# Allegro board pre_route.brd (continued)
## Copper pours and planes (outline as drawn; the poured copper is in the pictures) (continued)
XCVR_RX_N3C on TOP (solid shape): 263.03,247.12 263.04,247.12 263.19,246.89 263.25,246.61 263.25,244.26 263.72,242.76 263.73,242.67 263.74,242.63 263.74,242.56 263.24,242.56 263.24,242.27 262.52,242.27 262.52,242.57 262.04,242.57 262.04,242.67 262.06,242.77 262.16,243.14 262.29,243.5 262.53,244.25 262.53,246.62 262.38,247.76 262.39,247.76
XCVR_RX_N<1> on TOP (solid shape): 322.61,98.01 322.61,97.63 322.45,97.47 321.92,97.47 321.91,97.47 321.76,97.47 321.15,97.65 321.15,98 321.75,98.18 321.76,98.18 322.44,98.18
XCVR_RX_N<16> on TOP (solid shape): 312.34,249.81 312.34,249.3 312.17,249.2 311.44,249.2 310.77,249.19 310.6,249.26 310.53,249.43 310.57,249.57 310.69,249.66 311.43,249.91 312.17,249.91
XCVR_RX_N<17> on TOP (solid shape): 312.34,232.66 312.34,232.16 312.17,232.05 311.44,232.05 310.77,232.04 310.6,232.11 310.53,232.28 310.57,232.42 310.69,232.51 311.43,232.77 312.17,232.77
XCVR_RX_N<18> on TOP (solid shape): 312.34,266.95 312.34,266.45 312.17,266.34 311.44,266.34 310.77,266.33 310.6,266.4 310.53,266.57 310.57,266.71 310.69,266.8 311.43,267.06 312.17,267.06
XCVR_RX_N<19> on TOP (solid shape): 312.34,284.1 312.34,283.59 312.17,283.49 311.44,283.49 310.77,283.48 310.6,283.55 310.53,283.72 310.57,283.86 310.69,283.95 311.43,284.2 312.17,284.2
XCVR_RX_P0C on TOP (solid shape): 330.28,67 328.5,67 326.73,67.15 326.73,67.5 328.5,67.64 330.28,67.64
XCVR_RX_P0C on TOP (solid shape): 324.94,67.5 324.94,67.15 324.07,66.96 323.43,66.96 323.22,67.18 323.22,67.46 323.43,67.68 324.07,67.68
XCVR_RX_P1C on TOP (solid shape): 330.28,82.27 328.5,82.27 326.73,82.41 326.73,82.76 328.5,82.91 330.28,82.91
XCVR_RX_P1C on TOP (solid shape): 324.8,82.77 324.8,82.41 323.93,82.23 323.28,82.23 323.09,82.42 323.09,82.75 323.28,82.94 323.93,82.94
XCVR_RX_P2C on TOP (solid shape): 275.96,255.27 276.44,255.27 276.44,255.17 276.42,255.07 276.32,254.7 276.19,254.34 275.95,253.58 275.95,253.58 275.95,251.52 275.89,251.26 275.74,251.03 274.96,250.25 274.96,250.25 274.49,250.72 274.49,250.78 275.23,251.53 275.23,253.58 274.76,255.08 274.75,255.16 274.74,255.21 274.74,255.28 275.24,255.28 275.24,255.56 275.96,255.56
XCVR_RX_P3C on TOP (solid shape): 263.26,255.27 263.74,255.27 263.74,255.17 263.72,255.07 263.62,254.7 263.49,254.34 263.25,253.58 263.25,251.47 263.19,251.21 263.04,250.98 262.26,250.2 261.76,250.7 262.53,251.48 262.53,253.58 262.06,255.08 262.05,255.16 262.04,255.21 262.04,255.28 262.54,255.28 262.54,255.56 263.26,255.56
XCVR_RX_P<0> on TOP (solid shape): 322.71,67.44 322.71,67.18 322.49,66.96 322.01,66.96 321.85,66.96 321.24,67.14 321.24,67.5 321.85,67.67 321.85,67.68 322.47,67.68
XCVR_RX_P<1> on TOP (solid shape): 322.58,82.8 322.58,82.42 322.39,82.23 321.87,82.23 321.87,82.23 321.71,82.23 321.1,82.41 321.1,82.76 321.7,82.94 321.71,82.94 322.44,82.94
XCVR_RX_P<2> on TOP (solid shape): 274.45,250.19 274.45,249.94 274.41,249.9 274.51,249.8 274.08,249.37 274.08,249.36 273.97,249.29 273.84,249.26 273.07,249.27 272.9,249.33 272.83,249.5 272.83,249.52 272.88,249.66 273.01,249.74 273.57,249.86 273.94,250.24 273.94,250.24 274.01,250.31 274.1,250.22 274.32,250.32
XCVR_RX_P<3> on TOP (solid shape): 261.99,249.93 261.35,249.29 261.35,249.28 261.24,249.21 261.11,249.18 260.34,249.19 260.18,249.26 260.11,249.42 260.11,249.44 260.15,249.58 260.28,249.66 260.84,249.79 261.21,250.16 261.21,250.16 261.49,250.43
XCVR_RX_P<16> on TOP (solid shape): 310.8,248.78 311.44,248.64 312.17,248.64 312.34,248.54 312.34,248.03 312.17,247.93 311.44,247.93 310.65,248.33 310.59,248.37 310.54,248.45 310.53,248.54 310.6,248.71 310.77,248.78
XCVR_RX_P<17> on TOP (solid shape): 310.8,231.63 311.44,231.5 312.17,231.5 312.34,231.39 312.34,230.89 312.17,230.78 311.44,230.78 310.65,231.19 310.59,231.23 310.54,231.31 310.53,231.39 310.6,231.56 310.77,231.64
XCVR_RX_P<18> on TOP (solid shape): 310.8,265.92 311.44,265.79 312.17,265.79 312.34,265.68 312.34,265.18 312.17,265.07 311.44,265.07 310.65,265.48 310.59,265.52 310.54,265.6 310.53,265.68 310.6,265.85 310.77,265.93
XCVR_RX_P<19> on TOP (solid shape): 310.8,283.07 311.44,282.93 312.17,282.93 312.34,282.83 312.34,282.32 312.17,282.22 311.44,282.22 310.65,282.62 310.59,282.66 310.54,282.74 310.53,282.83 310.6,283 310.77,283.07
XCVR_TX_N<0> on TOP (solid shape): 330.28,112.75 328.5,112.75 326.73,112.89 326.73,113.24 328.5,113.39 330.28,113.39
XCVR_TX_N<1> on TOP (solid shape): 330.28,21.17 328.51,21.17 326.74,21.32 326.74,21.67 328.51,21.81 330.28,21.81
XCVR_TX_N<2> on TOP (solid shape): 289.12,242.76 289.13,242.67 289.14,242.63 289.14,242.56 288.64,242.56 288.64,242.27 287.92,242.27 287.92,242.57 287.44,242.57 287.44,242.67 287.46,242.77 287.56,243.14 287.69,243.5 287.93,244.25 287.93,244.26 288.65,244.26
XCVR_TX_N<3> on TOP (solid shape): 251.02,242.76 251.03,242.67 251.04,242.63 251.04,242.56 250.54,242.56 250.54,242.27 249.82,242.27 249.82,242.57 249.34,242.57 249.34,242.67 249.36,242.77 249.46,243.14 249.59,243.5 249.83,244.25 249.83,244.26 250.55,244.26
XCVR_TX_P<0> on TOP (solid shape): 330.28,127.99 328.5,127.99 326.73,128.13 326.73,128.48 328.5,128.63 330.28,128.63
XCVR_TX_P<1> on TOP (solid shape): 330.28,36.42 328.5,36.42 326.73,36.56 326.73,36.91 328.5,37.06 330.28,37.06
XCVR_TX_P<2> on TOP (solid shape): 288.66,255.27 289.14,255.27 289.14,255.17 289.12,255.07 289.02,254.7 288.89,254.34 288.65,253.58 288.65,253.58 287.93,253.58 287.46,255.08 287.45,255.16 287.44,255.21 287.44,255.28 287.94,255.28 287.94,255.56 288.66,255.56
XCVR_TX_P<3> on TOP (solid shape): 250.56,255.27 251.04,255.27 251.04,255.17 251.02,255.07 250.92,254.7 250.79,254.34 250.55,253.58 250.55,253.58 249.83,253.58 249.36,255.08 249.35,255.16 249.34,255.21 249.34,255.28 249.84,255.28 249.84,255.56 250.56,255.56
N24962500 on TOP (solid shape): 50.29,259.46 50.29,256.54 50.1,256.35 45.4,256.35 45.21,256.54 45.21,259.33 45.4,259.52 50.23,259.52

Small or netless copper shapes (teardrops, artwork), in the pictures only: 23 on TOP

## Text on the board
BOTTOM: COPYRIGHT   2003 | 100-0365000-01 REV.C | 18
Ref Des/Silkscreen Bottom: 9 | 6 | 5 | 1 | 3.3V PMC INTERFACE
User.Comments: REV. | FIGURE | 86.0 | 90.0 | 94.0 | SIZE | 62.0 | 67.0 | 55.0 | 118.0 | 126.0 | 138.0 | 47.0 | 36.0 | 42.0 | 49.0 | 52.0 | 170.0 | 32.0 | 10.0 | 56.0 | 120.0 | 125.0 | 128.0 | 24.0 | 28.0 | 85.0 | 21.0 | 2.0 | TOLERANCE | 3.0 | DRILL CHART (ALL UNITS ARE IN INCHES) | NON-PLATED | PLATED | 8 | 2 | 5 | QTY | 10 | 4 | 54 | 339 | 18 | 19 | 6112 | 212 | 28 | 249 | 11 | 6 | 362 | 256 | C
TOP: 1
Ref Des/Assembly Top: U53 | PRIMARY SIDE | SECONDARY SIDE
L2_GND1: 2
L3_IS1: 3
L4_IS2: 4
L5_PWR1: 5
L6_IS3: 6
L7_IS4: 7
L8_GND2: 8
L9_IS5: 9
L10_IS6: 10
L11_PWR2: 11
L12_IS7: 12
L13_IS8: 13
L14_GND3: 14
L15_IS9: 15
L16_IS10: 16
L17_PWR3: 17
DIMENSION: (2pl) | .250
User.11: 28. DELIVERY, PROVIDE 6 BOARDS TO ALTERA AND 2 BOARDS TO FLEXTRONICS FOR SMT AND | OF 100 MILS FROM ANY OTHER COPPER FEATURE ON THE BOARD. | THERMAL TESTING. | 26. COPPER THIEVING SHALL BE APPLIED WHEREVER REQUIRED BUT MUST HAVE A SPACING | 27. REMOVE ALL UNCONNECTED VIA PADS IN INNER LAYERS. | 22. VENDOR TO PROVIDE 2 SOLDER SAMPLES WITH FIRST SHIPMENT. | 23. DETAILS NOT SPECIFIED ARE AT MANUFACTURER'S OPTION, HOWEVER | FINAL APPROVAL MUST BE OBTAINED. | 24  THESE HOLES MAY BE PLATED SHUT OR SOLDER FILLED. | 25. PLUG VIA HOLES FROM         SIDE WITH SR-1000 OR EQUIVALENT MATERIAL, CLEAR | UV MASK IS ACCEPTABLE. PLUG HEIGHT NOT TO EXCEED 0.003 OVER FINISHED PLATING HEIGHT. | 21. VENDOR TO PROVIDE                     ONE CROSS SECTION PER LOT WITH SHIPMENT. | INCHES MINIMUM ELECTROLESS NICKEL (Ni) FOLLOWED BY 3-8 MICRO INCHES | IMMERSION GOLD (Au). | 17  FINISH IS SOLDER MASK OVER BARE COPPER (SMOBC) BOTH SIDES WITH 150 MICRO | 18  SILKSCREEN USING WHITE NONCONDUCTIVE INK. NO INK TO APPEAR ON EXPOSED | COPPER SUCH AS PLATED THROUGH HOLE PADS AND SURFACE MOUNT LANDS. INK | ON SOLDER MASK COVERED PADS IS PERMISSIBLE. CLIPPING OF SILKSCREEN | 0.008 MAX. FROM PADS IS PERMITTED IF REQUIRED. | 19. 100% CONTINUITY AND ISOLATION ELECTRICAL TESTING PER CURRENT IPC TEST METHODS | REQUIRED FOR EVERY PCB. FINAL PCB TEST DATA MUST BE CROSS-REFERENCED TO | IPC-D-356 FILE, NEUTRAL FILE OR NETLIST PROVIDED. | 20  CONTROLLED IMPEDANCE LINES ARE AS FOLLOWS: | NOTES UNLESS OTHERWISE SPECIFIED: | 1. ALTERA PCB PART NUMBER: P/N 100-0365000-01 REV.C | 2. THIS DRAWING IS VIEWED FROM THE PRIMARY OR TOP SIDE OF PCB. | 3  FABRICATION OF THIS PCB SHALL BE IN CONFORMANCE WITH THE FOLLOWING SPECIFICATIONS: | 4. FABRICATION OF THIS PCB TO BE ACCEPTABLE TO IPC-A-600 CLASS 2(LATEST REVISION). | 5. ALL DIMENSIONAL LIMITS APPLY AFTER PLATING OR PROCESSING. | 6. TOLERANCES OF DATUM HOLE TO:  BOARD EDGE LOCATIONS +/- 0.010. | DRILLED HOLE LOCATIONS +/- 0.003. | V-SCORE LOCATIONS +/- 0.010 (IF APPLICABLE). | 7  BASE MATERIAL:                , MIN. Tg OF     DEGREES C. | 8. FLAME CLASS: UL 94V-0 & MUST MEET REQUIREMENTS OF UL796. | 9. MANUFACTURER MUST BE UL RECOGNIZED TO PRODUCE THIS PRODUCT SUCH THAT | IT MEETS 170 DEGREES CELSIUS MAXIMUM OPERATING TEMPERATURE (MOT). | 10  THE FOLLOWING MUST BE MARKED OR ETCHED ON SECONDARY SIDE OF PCB IN AREA SHOWN: | DATE CODE. | UL RECOGNIZED VENDOR ID, UL TYPE DESIGNATION AND/OR MARKINGS WHICH REFLECT | THE SPECIFIED FLAME CLASS AND MAXIMUM OPERATING TEMPERATURE RATINGS. | 11. BOW & TWIST SHALL BE DETERMINED BY PHYSICAL MEASUREMENT AND PERCENTAGE CALCULATION | IN ACCORDANCE WITH IPC-TM-650, METHOD 2.4.22. BOW AND TWIST MAY NOT EXCEED 0.7%. | 12. HOLE/SLOT PLATING = 0.001 MIN. AVERAGE / 0.0008 ABSOLUTE MIN. PLATING. | HOLE/SLOT DIAMETERS ARE SPECIFIED AFTER PLATING (SEE HOLE SCHEDULE). | 13. SMEAR REMOVAL SHALL NOT ETCHBACK GREATER THAN 0.001. | 14. INTERNAL ANNULAR RING 0.001 MINIMUM. EXTERNAL ANNULAR RING 0.002 MINIMUM. BOTH | ARE MEASURED AT LINE TO PAD ENTRY. NON-FUNCTIONAL INNER LAYER PADS MAY BE REMOVED. | SNOWMAN/TEAR DROPPING OF TRACE TO PAD JUNCTION IS PERMITTED PROVIDED MINIMUM | METAL-TO-METAL ARTWORK SPACINGS ARE NOT COMPROMISED. | 15. FINISHED CONDUCTOR WIDTH NOT TO BE REDUCED MORE THAN 20% OF MINIMUM WIDTH FROM | ARTWORK SUPPLIED. FINISHED CONDUCTOR SPACING NOT TO BE REDUCED MORE THAN 20% OF | MINIMUM SPACING FROM ARTWORK SUPPLIED. | 16  SOLDER MASK IS LIQUID PHOTO IMAGEABLE WITH GLOSSY FINISH AND COLORED GREEN | ACCORDANCE WITH IPC-SM-840C CLASS T. REGISTRATION TO BE WITHIN +/-0.003 OF ITS | RESPECTIVE OUTER CIRCUIT LAYERS. VENDOR MAY ADJUST SOLDERMASK WHEREVER SOLDERMASK | PAD ARE THE SAME SIZE (1:1) TO PROVIDE UP TO .003" MAXIMUM CLEARANCE FROM MASK TO | PAD PROVIDED NO ADJACENT COPPER IS EXPOSED AND NO CONFLICT IS PRODUCED WITH ANY | STATED "VIA TENTING/PLUGGING" REQUIREMENTS (IF APPLICABLE). | NOTE THAT THERE ARE AREAS ON PRIMARY SIDE THAT ARE CLEAR OF SOLDERMASK. | SECONDARY SIDE WILL REQUIRED VIAS TO BE EXPOSED. | IN | 10 | 20 | 24 | 16 | 7 | 3 | 18 | 17 | DETAIL | SCALE: NONE | (CROSS SECTION) | A
User.41: J. MANNING
User.43: 9330 Scranton Road | Suite 400 | San Diego, CA | 92121 | NOTES: UNLESS OTHERWISE SPECIFIED | 1. | 2. | 3. | 4. | ASSEMBLE BOARD PER IPC-A-610(LATEST REVISION) STANDARD | HANDLE MOISTURE SENSITIVE DEVICES(MSD) PER MANUFACTURE'S | CALL OUT ON MSD LABEL. IF MSD LABEL IS MISSING OR NOT LEGIBLE | THEN ALL PLASTIC PACKAGED COMPONENTS ARE TO BE CONSIDERED MSD | LEVEL 6 AND USE EIA/JEP 113-A FOR HANDLING. | REWORK MUST BE APPROVED BY CUSTOMER BEFORE BEING ACCEPTIBLE. | USE IPC-R-700(LATEST REVISION) FOR ALL PCBA REWORK APPROVED. | SQUARE PIN PADS DENOTE PIN 1 OF ICs/CONNECTORS, POSITIVE END | FOR CAPACITORS OR CATHODE END FOR DIODES. | 130-0365000-01 | Altera Corporation
User.45: ETHERNET | 10/100 | GND | POWER | ATX | TEL_ON | GND_PLL | ATX_ON | STRATIX_PB_[0:3] | 3.3V_LIN_EN | GX_CLR | STRATIX_GX_PB_[0:3] | S_CLR | SANTA CRUZ INTERFACE | STRATIX | GX_LED | GP FLASH | STRATIX_LED | 1.5V_GX_INT | MICTOR | 3.3V_GX_IO | 3.3V_S_IO | RMT | JTAG | CONFIG SCHEME | PS HDR | STD | 3.3V | CLKS_SOURCE | 3.3V_XCVR | GND_RTN | -48V_IN | PGM[2:0] | CLK_OUTA | STRATIX GX USER[7:0] | STRATIX USER[7:0] | GND_HSSI | STRATIX GX | CLK_OUTB | EXT_CLK_IN_P | CLK_DIV_A | 1.25V VREF | RU/LU | EXT_CLK_IN_N | 1.25V | DIV_20_LVPECL | CLK_DIV_B | OUT_P | OUT_N | CLK_IN_N | DISPLAY | DIV_20_LVTTL_OUT | CLK_IN_P | EXT CLK1 | XCVR HMZD INTERFACE | EXT CLK2 | TRIG_155_52 | TRIG_156_25 | OSC | SMA | 156.25MHZ | SELECT | CLOCK | 155.52MHZ | 33MHZ SMA | INPUT | INPUT2_GX_N | INPUT2_GX_P | XTAL3_OUT_TP1 | SPI-4.2 HEADERS | HSSI | 15P | 14P | 15N | 14N | XPAK | P  N | INPUT4_GX | RECOV | REFCLKB | CLK2 | INPUT1_GX_N | INPUT1_GX_P | 1.5V_PLL | TX_N3 | TX_P3 | CLK3 | RX_N3 | RX_P3 | CLK1 | MDIO HDR | + | 1.5V_XCVR | STRATIX GX MICTOR | INTERFACE | SFP | RX_N2 | RX_P2 | CLK0 | CLK_OUT_N | CLK_OUT_P | TX_N0 | TX_P0 | TX_N1 | TX_P1 | XCVR7 | XCVR5 | XCVR4 | XCVR6 | DPA | TX_P2 | TX_N2 | CLK4 | CONNECTORS | INPUT3_GX_P | RX_P0 | RX_N0 | RX_N1 | RX_P1 | HSSDC2 | XCVR19 | XCVR16 | XCVR17 | XCVR18 | INPUT3_GX_N | NO | YES | PS_HDR | EPC16 | STRATIX GX RS232 | (BOTTOM) | STRATIX RS232 | STRATIX BYPASS | STRATIX GX BYPASS | (TOP) | OFF | GX CLR | RESET | S_CONF_DONE | GX_CONF_DONE | 1.5V_S_INT | 2.5V_GX_IO | DATA | GEN | 2.5V | STRATIX TEST HDR | DDR DIMM | BRIDGE HEADERS | STRATIX GX TEST HDR | 130-0365000-01 | MADE IN USA | L01/TOP - .5 Oz Cu BEFORE PLATING | L02/PLN - 1 Oz Cu | L03/SIG - .5 Oz Cu | L04/SIG - .5 Oz Cu | L05/PLN - 1 Oz Cu | L06/SIG - .5 Oz Cu | L07/SIG - .5 Oz Cu | L08/PLN - 1 Oz Cu | L09/SIG - .5 Oz Cu | L010/SIG - .5 Oz Cu | L011/PLN - 1 Oz Cu | L012/SIG - .5 Oz Cu | L013/SIG - .5 Oz Cu | L014/PLN - 1 Oz Cu | L015/SIG - .5 Oz Cu | L016/SIG - .5 Oz Cu | L017/PLN - 1 Oz Cu | L018/BOT - .5 Oz Cu BEFORE PLATING | PREPREG - 3.6 MILS THK | CORE    - 4 MILS THK | PREPREG - 6.1 MILS THK | PREPREG - 4.5 MILS THK | CORE    - 5 MILS THK | 0.7 MILS THK | 1.4 MILS THK | H) CONTINUED.... | L12 | L13 | L14 | L15 | L16 | L17 | L18 | ONE TEST COUPON AND | 3.7 | PRIMARY | 4 | 5.5 | 5.3 | BOARD LAYER 16 OF 18, INNER SIGNAL-10 | BOARD LAYER 13 OF 18, INNER SIGNAL-8 | BOARD LAYER 12 OF 18, INNER SIGNAL-7 | BOARD LAYER 11 OF 18, POWER PLANE-2 | BOARD LAYER 2 OF 18, GND PLANE-1 | BOARD LAYER 14 OF 18, GND PLANE-3 | BOARD LAYER 5 OF 18, PWR PLANE-1 | FILM SHEET 14 OF 25 | BOARD LAYER 17 OF 18, POWER PLANE-3 | BOARD LAYER 15 OF 18, INNER SIGNAL-9 | FILM SHEET 13 OF 25 | BOARD LAYER 8 OF 18, GND PLANE-2 | FILM SHEET 17 OF 25 | FILM SHEET 12 OF 25 | FILM SHEET 16 OF 25 | FILM SHEET 11 OF 25 | FILM SHEET 5 OF 25 | FILM SHEET 2 OF 25 | FILM SHEET 8 OF 25 | FILM SHEET 15 OF 25 | H) L3,L4,L6,L7,L9,L10,L12,L13,L16; TIGHTLY EDGE-COUPLED MICROSTRIP | DESIRED IMEPDANCE: 100 OHMS DIFFERENTIAL. USE DIMENSIONS PROVIDED | BY TITAN. BOARD IS ROUTED WITH 5 MIL LINES WITH 5 MIL SPACING. | L10 | L11 | L3 | L4 | L5 | L6 | L7 | L8 | L9 | L1 | L2 | F) L1 HIGH SPEED LINES, DESIRED IMPEDANCE: 100 OHMS DIFFERENTIAL | G) L13 AND L15, EDGE-COUPLED STRIPLINE, DESIRED IMPEDANCE: 100 OHMS | (SHOULD NOT HAVE SOLDERMASK) | DIFFERENTIAL. | SIGNAL | 6 | 4.95 | 5 | 14 | 15.05 | 15 | IPC-6011 CLASS 2 (GENERIC). | a) TOLERANCE (ALL LINES) +/- 5%, | B) L1 HIGH SPEED LINES AT EDGE LAUNCH SMA PINS, DESIRED IMPEDANCE: 50 OHMS | C) L1 HIGH SPEED LINES AT CAPACITOR PAD (0402 SIZE COMPONENT) AFTER EDGE | D) L1 HIGH SPEED LINES AT UPRIGHT SMA PIN, DESIRED IMPEDANCE: 50 OHMS | E) L1 HIGH SPEED LINES AT 0402 CAP PAD, DESIRED IMPEDANCE: 50 OHMS | (NO SOLDERMASK). | LAUNCH SMA. DESIRED IMPEDANCE: 50 OHMS (NO SOLDERMASK) | (NO SOLDERMASK) | NOTE: THERE IS A GRADUAL TRANSISTION FROM CONFIGURATION B TO C. | NOTE: THERE IS A GRADUAL TRANSISTION FROM CONFIGURATION D TO E. | FR4 GLASS EPOXY | 20 | 28 | 67 | 170 | A | (TITAN DIMENSIONS) | DEVELOPMENT | BOARD | .093 | +/-.005
